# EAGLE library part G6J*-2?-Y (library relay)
Surface-Mounting Signal Relay - G6J-Y 5.7 x 10.6 x 9 mm Source: http://www.omroncomponents.eu/ .. K125-E2-02-X.pdf
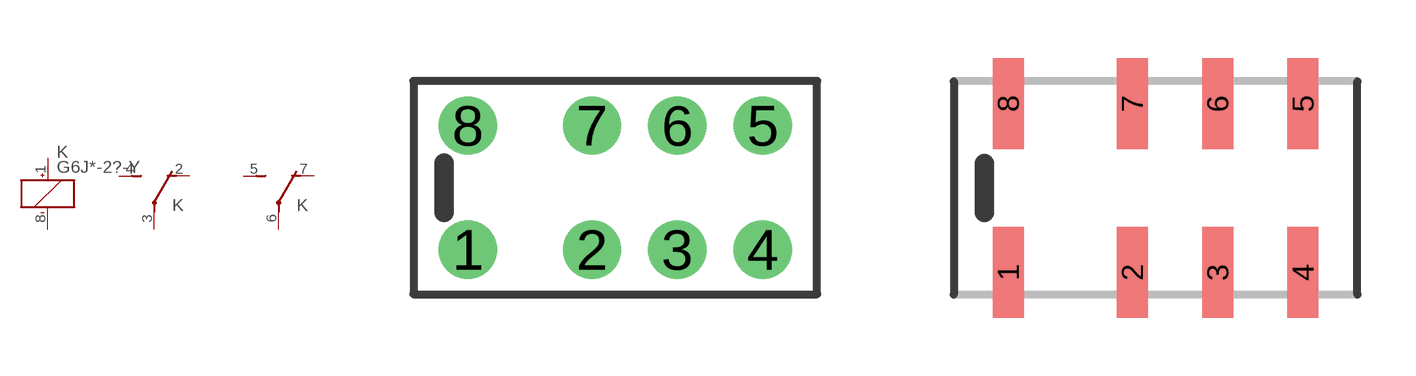
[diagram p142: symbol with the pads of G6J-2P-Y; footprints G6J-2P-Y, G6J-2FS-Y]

Designator prefix K; gates 1=K+- 2=U 3=U

## G6J-2P-Y (MF: OMRON COMPONENTS USA; MPN: G6J-2P-Y-DC12; OC_FARNELL: unknown; OC_NEWARK: 70J9830), G6JU-2P-Y (MF: OMRON COMPONENTS USA; MPN: G6JU-2P-Y-DC12; OC_FARNELL: unknown; OC_NEWARK: 70J9842)  [G6J-2P-Y]
1  1:+  pas
2  2:O  pas
3  2:P  pas
4  2:S  pas
5  3:S  pas
6  3:P  pas
7  3:O  pas
8  1:-  pas

## G6J-2FS-Y (MPN: G6J-2FS-Y DC4.5; OC_FARNELL: unknown; OC_NEWARK: 04M9910), G6JU-2FS-Y (OC_FARNELL: unknown; OC_NEWARK: unknown)  [G6J-2FS-Y]
Pads as for G6J-2P-Y

## G6J-2FL-Y (MPN: G6J-2FL-Y-TR DC4.5; OC_FARNELL: 1798618; OC_NEWARK: 04M9907), G6JU-2FL-Y (MPN: G6JU-2FL-Y DC3; OC_FARNELL: unknown; OC_NEWARK: 04M9916)  [G6J-2FL-Y]
Pads as for G6J-2P-Y

## Footprint G6J-2P-Y (pad centres in mm)
Signal Relay - G6J-Y 5.7 x 10.6 x 9 mm Source: http://www.omroncomponents.eu/ .. K125-E2-02-X.pdf
drill 0.9 pad 1.5 round: 1 -3.2,-1.6; 2 0,-1.6; 3 2.2,-1.6; 4 4.4,-1.6; 5 4.4,1.6; 6 2.2,1.6; 7 0,1.6; 8 -3.2,1.6

## Footprint G6J-2FS-Y (pad centres in mm)
Signal Relay - G6J-Y 5.7 x 10.6 x 9 mm Source: http://www.omroncomponents.eu/ .. K125-E2-02-X.pdf
smd 0.8 x 2.35: 1 -3.2,-2.175; 2 0,-2.175; 3 2.2,-2.175; 4 4.4,-2.175; 5 4.4,2.175; 6 2.2,2.175; 7 0,2.175; 8 -3.2,2.175

## Footprint G6J-2FL-Y (pad centres in mm)
Signal Relay - G6J-Y 5.7 x 10.6 x 9 mm Source: http://www.omroncomponents.eu/ .. K125-E2-02-X.pdf
smd 0.8 x 3.2: 1 -3.2,-2.6; 2 0,-2.6; 3 2.2,-2.6; 4 4.4,-2.6; 5 4.4,2.6; 6 2.2,2.6; 7 0,2.6; 8 -3.2,2.6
